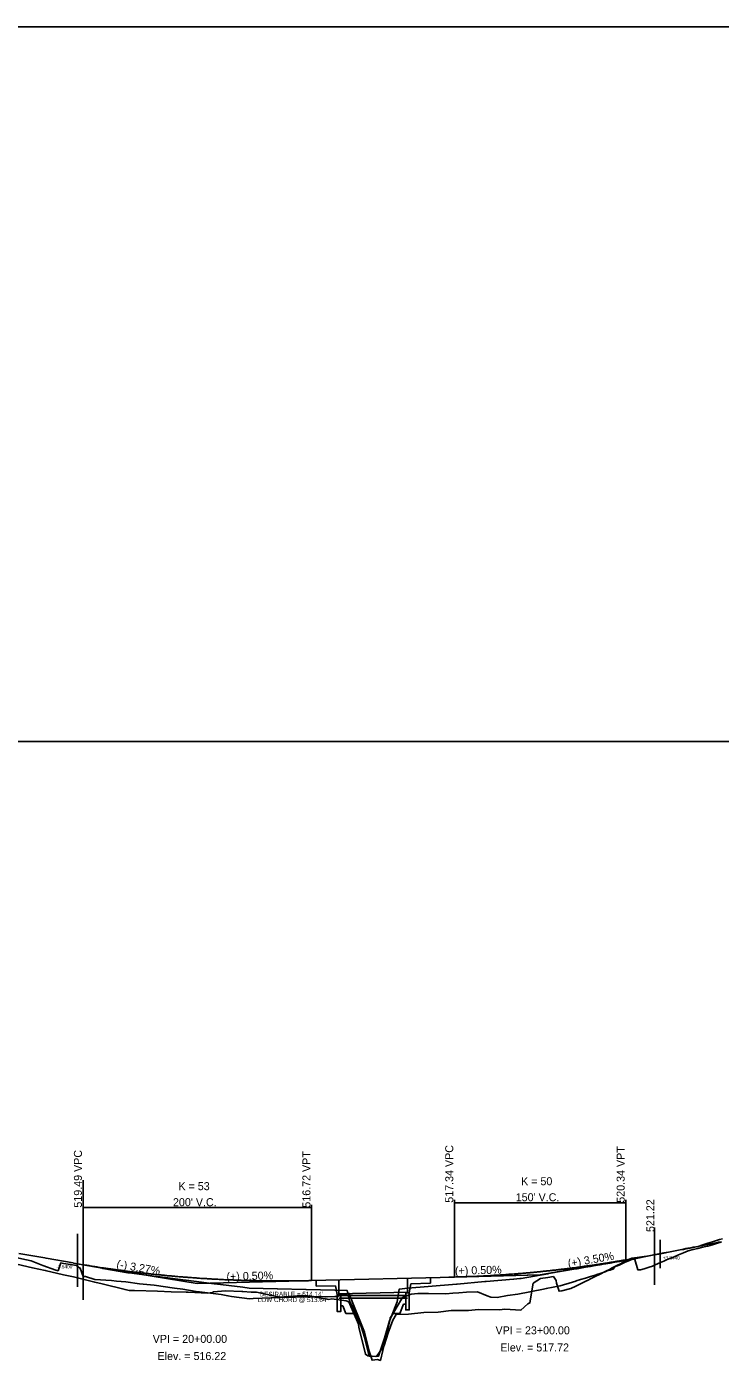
# Model space of a CAD drawing. Extents: x 2167726 to 2171326, y 1079832 to 1082032.
# Drawn here: x 2169001 to 2169608, y 1080863 to 1082032 of the extents above; entities that cross this region are included whole.
import ezdxf

# ---------------------------------------------------------------- set-up
doc = ezdxf.new("R2010")
doc.units = 0
for name, color, linetype in [('BR_CONCRETE', 7, 'Continuous'), ('BR_EXIST_GROUND_LT', 7, 'Continuous'), ('BR_EXIST_GROUND_RT', 7, 'Continuous'), ('BR_USER NOTES', 7, 'Continuous'), ('RD_DDB_GradeTX', 7, 'Continuous'), ('RD_DDB_Profile_EX', 7, 'Continuous'), ('RD_DDB_Profile_Lbl', 7, 'Continuous'), ('RD_DDB_Profile_PR', 7, 'Continuous'), ('RD_DDB_StripGrade', 7, 'Continuous'), ('RD_DDB_VCLbl', 7, 'Continuous'), ('RD_SHT_IplotShp', 7, 'Continuous'), ('RD_SHT_ShtClip', 7, 'Continuous')]:
    doc.layers.add(name, color=color, linetype=linetype)

msp = doc.modelspace()

# ---------------------------------------------------------------- linework, layer by layer
at = {"layer": 'BR_CONCRETE'}
for p, q in [((2169254.2, 1080935.2), (2169254.2, 1080930.2)), ((2169254.2, 1080930.2), (2169271.2, 1080930.6)), ((2169272.7, 1080923), (2169271.2, 1080930.6)), ((2169274.2, 1080923.4), (2169274.2, 1080935.7)), ((2169334.2, 1080924.9), (2169334.2, 1080937.2)), ((2169335.7, 1080924.5), (2169337.2, 1080932.3)), ((2169337.2, 1080932.3), (2169354.2, 1080932.7)), ((2169354.2, 1080932.7), (2169354.2, 1080937.7)), ((2169274.2, 1080923.4), (2169334.2, 1080924.9)), ((2169274.2, 1080923), (2169274.2, 1080923.4)), ((2169334.2, 1080924.5), (2169334.2, 1080924.9)), ((2169275.7, 1080913), (2169277.7, 1080913)), ((2169332.7, 1080914.5), (2169330.7, 1080914.5))]:
    msp.add_line(p, q, dxfattribs=at)
for points in [[(2169272.7, 1080923), (2169275.7, 1080923), (2169275.7, 1080908), (2169272.7, 1080908)], [(2169335.7, 1080924.5), (2169332.7, 1080924.5), (2169332.7, 1080909.5), (2169335.7, 1080909.5)]]:
    msp.add_lwpolyline(points, close=True, dxfattribs=at)
for points in [[(2169277.7, 1080913), (2169280.3, 1080906.4), (2169288.7, 1080906.4)], [(2169330.7, 1080914.5), (2169327.5, 1080906.4), (2169321.2, 1080906.4)]]:
    msp.add_lwpolyline(points, dxfattribs=at)
at = {"layer": 'BR_EXIST_GROUND_LT'}
msp.add_lwpolyline([(2168992.2, 1080949.5), (2169006, 1080946.2), (2169017.1, 1080944), (2169033.1, 1080940.1), (2169041.9, 1080938.3), (2169060.4, 1080933.7), (2169066.8, 1080932.4), (2169087, 1080927.2), (2169090.6, 1080926.5), (2169095.2, 1080926.3), (2169115.5, 1080925.9), (2169127.3, 1080925.3), (2169140.4, 1080925), (2169142.2, 1080925), (2169159.3, 1080924), (2169163.5, 1080924.7), (2169164.3, 1080925.3), (2169175, 1080926.1), (2169189.3, 1080925.6), (2169190.1, 1080925.5), (2169197.3, 1080925.1), (2169201.9, 1080925), (2169222, 1080920.7), (2169241.5, 1080922), (2169242.6, 1080922), (2169246.8, 1080921.9), (2169265.2, 1080918.7), (2169268, 1080919.1), (2169280.4, 1080917.3), (2169282.8, 1080916.5), (2169291.3, 1080896.9), (2169291.7, 1080894.3), (2169297.4, 1080870.7), (2169299.5, 1080869.2), (2169306.9, 1080868.7), (2169313.6, 1080878.3), (2169317.2, 1080889.3), (2169321.4, 1080900.6), (2169324.1, 1080905.4), (2169334.9, 1080905.8), (2169348.4, 1080907.3), (2169361, 1080907.6), (2169372.5, 1080908.9), (2169387.5, 1080908.9), (2169396.3, 1080909.9), (2169414.8, 1080909.5), (2169419.4, 1080910), (2169433.4, 1080909.2), (2169439.6, 1080914.9), (2169441.3, 1080915.5), (2169444.2, 1080932.7), (2169450.5, 1080936.9), (2169457, 1080937.9), (2169461.9, 1080938.6), (2169464.2, 1080935.1), (2169464.7, 1080932.9), (2169466.8, 1080925.8), (2169469.2, 1080926.1), (2169477.1, 1080928.1), (2169481.4, 1080930.2), (2169485.7, 1080932.3), (2169490.1, 1080934.5), (2169492.3, 1080935.5), (2169494.3, 1080936.5), (2169498.5, 1080938.6), (2169502.8, 1080940.8), (2169507.1, 1080943), (2169511.4, 1080945.2), (2169512.7, 1080945.9), (2169515.7, 1080947.3), (2169518.1, 1080948.5), (2169519.9, 1080949.5), (2169524.2, 1080951.7), (2169525.3, 1080952.3), (2169526, 1080952.7), (2169528.5, 1080953.9), (2169530.4, 1080954.8), (2169532.8, 1080955.1), (2169537.1, 1080955.7), (2169541.3, 1080956.3), (2169545.6, 1080956.9), (2169549.4, 1080957.5), (2169549.9, 1080957.6), (2169554.2, 1080958.5), (2169555.3, 1080958.8), (2169558.4, 1080959.3), (2169562.7, 1080960), (2169567, 1080960.8), (2169571.3, 1080961.6), (2169574.6, 1080962.2), (2169575.6, 1080962.5), (2169577.9, 1080963.1), (2169579.8, 1080963.5), (2169582, 1080963.9), (2169584.1, 1080964.3), (2169588.5, 1080965), (2169592.7, 1080966.3), (2169597, 1080967.7), (2169601.2, 1080969), (2169605.5, 1080970.4), (2169607.2, 1080971), (2169609.8, 1080971.5)], dxfattribs=at)
at = {"layer": 'BR_EXIST_GROUND_RT'}
msp.add_lwpolyline([(2168989.8, 1080955.7), (2169004.8, 1080952.3), (2169015.1, 1080948.4), (2169026.3, 1080944.1), (2169028.3, 1080943.7), (2169030.8, 1080950.5), (2169033.1, 1080950), (2169039.3, 1080949.3), (2169044.4, 1080948.2), (2169047.5, 1080946.1), (2169047.8, 1080946), (2169050.4, 1080938.7), (2169052.4, 1080938.8), (2169060.5, 1080936.1), (2169075.2, 1080935.1), (2169079.5, 1080934.7), (2169087.6, 1080934.1), (2169099.6, 1080932.2), (2169112.5, 1080931.2), (2169130.3, 1080928.4), (2169137.5, 1080927.6), (2169149.1, 1080925.7), (2169152, 1080925.4), (2169171, 1080922.8), (2169177, 1080921.8), (2169180.1, 1080921.2), (2169196, 1080919), (2169199.2, 1080919.5), (2169214.8, 1080919.9), (2169221.2, 1080920.2), (2169223.5, 1080920.2), (2169245.8, 1080920.8), (2169253.9, 1080920.8), (2169270.6, 1080921.1), (2169272.3, 1080921.2), (2169282.9, 1080924), (2169296.5, 1080890), (2169300.5, 1080873.3), (2169303.2, 1080865.4), (2169307.9, 1080866), (2169310.4, 1080865.2), (2169318.7, 1080900.3), (2169319, 1080902.5), (2169320.2, 1080904.1), (2169321.9, 1080907), (2169324.2, 1080910.9), (2169329.7, 1080920.2), (2169337.3, 1080923.2), (2169343.3, 1080923.8), (2169352.4, 1080923.7), (2169367.6, 1080923.5), (2169373.9, 1080924.1), (2169379, 1080924.5), (2169385.9, 1080925.1), (2169395.3, 1080925.2), (2169403.9, 1080921.9), (2169407, 1080920.7), (2169412.5, 1080920.2), (2169421.7, 1080922.1), (2169430.8, 1080923.3), (2169453.3, 1080927.7), (2169455.6, 1080928.1), (2169467.8, 1080930.6), (2169478.7, 1080933.7), (2169481.4, 1080934.7), (2169481.9, 1080934.9), (2169485.7, 1080936), (2169490, 1080937.3), (2169494.3, 1080938.6), (2169498.5, 1080939.9), (2169500, 1080940.3), (2169502.8, 1080941.3), (2169507.1, 1080942.9), (2169509, 1080943.6), (2169511.4, 1080944.3), (2169513.5, 1080945), (2169514.2, 1080945.2), (2169515.9, 1080947.3), (2169517.9, 1080948), (2169518.4, 1080948.3), (2169519.3, 1080948.6), (2169519.9, 1080948.9), (2169524.2, 1080950.8), (2169528.5, 1080952.6), (2169531.1, 1080953.7), (2169532.4, 1080953.5), (2169532.8, 1080953.5), (2169533.2, 1080953.5), (2169535.7, 1080944.6), (2169537.1, 1080944.6), (2169538.1, 1080944.6), (2169541.3, 1080945.5), (2169545.6, 1080946.8), (2169548.5, 1080947.6), (2169549.9, 1080948.3), (2169554.2, 1080950.2), (2169558.4, 1080952.2), (2169560.4, 1080953), (2169562.9, 1080954), (2169567, 1080955.7), (2169571.3, 1080957.5), (2169575.6, 1080959.3), (2169579.8, 1080961.1), (2169584.1, 1080962.2), (2169588.4, 1080963.2), (2169592.7, 1080964.2), (2169596.3, 1080965.1), (2169597, 1080965.3), (2169601.2, 1080966.5), (2169604.6, 1080967.5), (2169605.5, 1080967.8), (2169608.9, 1080968.7)], dxfattribs=at)
at = {"layer": 'BR_USER NOTES'}
for p, q in [((2169050.2, 1081022.9), (2169050.2, 1080918.4)), ((2169550.2, 1080981.5), (2169550.2, 1080931.5)), ((2169045.2, 1080976), (2169045.2, 1080929.7)), ((2169555.2, 1080970.8), (2169555.2, 1080945.9)), ((2169550.2, 1080957.6), (2169555.2, 1080958.5)), ((2169050.2, 1080948.9), (2169045.2, 1080949.8)), ((2169274.2, 1080922.2), (2169334.2, 1080922.2)), ((2169274.2, 1080919.7), (2169334.2, 1080919.7))]:
    msp.add_line(p, q, dxfattribs=at)
at = {"layer": 'RD_DDB_GradeTX'}
for p, q in [((2169529, 1080953.9), (2169450.2, 1080940.1)), ((2169525.2, 1080953.2), (2169450.2, 1080940.1)), ((2169071.2, 1080945.5), (2169150.2, 1080932.6)), ((2169230.2, 1080934.6), (2169150.2, 1080932.6)), ((2169370.2, 1080938.1), (2169450.2, 1080940.1)), ((2169375.2, 1080938.2), (2169450.2, 1080940.1))]:
    msp.add_line(p, q, dxfattribs=at)
at = {"layer": 'RD_DDB_Profile_EX'}
msp.add_lwpolyline([(2168993.9, 1080958.9), (2169016.8, 1080954.9), (2169017.8, 1080954.7), (2169041.6, 1080950.5), (2169041.9, 1080950.4), (2169066.8, 1080946), (2169067.6, 1080945.8), (2169089.4, 1080941.9), (2169089.9, 1080941.8), (2169090.5, 1080941.8), (2169114.9, 1080938.7), (2169115.5, 1080938.6), (2169139.9, 1080935.6), (2169140.5, 1080935.5), (2169164.9, 1080932.4), (2169165.5, 1080932.4), (2169189.9, 1080929.3), (2169195.5, 1080928.6), (2169220.1, 1080928), (2169220.5, 1080928), (2169245.2, 1080927.3), (2169245.5, 1080927.3), (2169270.5, 1080926.7), (2169281.4, 1080926.4), (2169283.4, 1080917.5), (2169290.4, 1080902.9), (2169293.7, 1080895), (2169296.4, 1080885.6), (2169300.7, 1080869.1), (2169306.1, 1080868.8), (2169308.8, 1080869.1), (2169313.9, 1080884.7), (2169318.3, 1080899.8), (2169320.3, 1080904), (2169325, 1080916.4), (2169327, 1080927.7), (2169334.4, 1080928.4), (2169352.2, 1080929.9), (2169377, 1080932), (2169377.6, 1080932.1), (2169401.9, 1080934.2), (2169403.1, 1080934.3), (2169426.9, 1080936.3), (2169427.3, 1080936.3), (2169432.5, 1080936.8), (2169433.7, 1080937), (2169457.1, 1080941.1), (2169457.7, 1080941.2), (2169481.4, 1080945.3), (2169481.7, 1080945.3), (2169482.6, 1080945.5), (2169485.7, 1080946), (2169490, 1080946.8), (2169494.3, 1080947.5), (2169498.5, 1080948.2), (2169502.8, 1080949), (2169506.8, 1080949.7), (2169507.1, 1080949.7), (2169507.6, 1080949.8), (2169511.4, 1080950.4), (2169515.7, 1080951.2), (2169519.9, 1080951.9), (2169524.2, 1080952.6), (2169525.9, 1080952.9), (2169526.7, 1080953), (2169528.5, 1080953.4), (2169532.8, 1080954.2), (2169537.1, 1080955), (2169541.3, 1080955.9), (2169545.6, 1080956.7), (2169550.1, 1080957.6), (2169551.6, 1080957.9), (2169554.2, 1080958.3), (2169558.4, 1080959.2), (2169562.7, 1080960), (2169567, 1080960.8), (2169571.3, 1080961.6), (2169574.3, 1080962.2), (2169575.6, 1080962.4), (2169576.7, 1080962.6), (2169579.8, 1080963.2), (2169581, 1080963.4), (2169581.5, 1080963.5), (2169584.1, 1080964.1), (2169588.4, 1080964.9), (2169592.7, 1080965.8), (2169597, 1080966.6), (2169601.2, 1080967.5), (2169604, 1080968), (2169605.5, 1080968.4), (2169606.4, 1080968.6), (2169608.8, 1080969)], dxfattribs=at)
at = {"layer": 'RD_DDB_Profile_PR'}
for p, q in [((2169525.2, 1080953.2), (2169550.2, 1080957.6)), ((2169250.2, 1080935.1), (2169375.2, 1080938.2))]:
    msp.add_line(p, q, dxfattribs=at)
for points in [[(2169375.2, 1080938.2), (2169378.2, 1080938.3), (2169381.2, 1080938.4), (2169384.2, 1080938.5), (2169387.2, 1080938.6), (2169390.2, 1080938.7), (2169393.2, 1080938.8), (2169396.2, 1080939), (2169399.2, 1080939.1), (2169402.2, 1080939.2), (2169405.2, 1080939.4), (2169408.2, 1080939.6), (2169411.2, 1080939.8), (2169414.2, 1080939.9), (2169417.2, 1080940.1), (2169420.2, 1080940.3), (2169423.2, 1080940.6), (2169426.2, 1080940.8), (2169429.2, 1080941), (2169432.2, 1080941.3), (2169435.2, 1080941.5), (2169438.2, 1080941.8), (2169441.2, 1080942), (2169444.2, 1080942.3), (2169447.2, 1080942.6), (2169450.2, 1080942.9), (2169453.2, 1080943.2), (2169456.2, 1080943.5), (2169459.2, 1080943.8), (2169462.2, 1080944.2), (2169465.2, 1080944.5), (2169468.2, 1080944.9), (2169471.2, 1080945.2), (2169474.2, 1080945.6), (2169477.2, 1080946), (2169480.2, 1080946.3), (2169483.2, 1080946.7), (2169486.2, 1080947.1), (2169489.2, 1080947.6), (2169492.2, 1080948), (2169495.2, 1080948.4), (2169498.2, 1080948.8), (2169501.2, 1080949.3), (2169504.2, 1080949.8), (2169507.2, 1080950.2), (2169510.2, 1080950.7), (2169513.2, 1080951.2), (2169516.2, 1080951.7), (2169519.2, 1080952.2), (2169522.2, 1080952.7), (2169525.2, 1080953.2)], [(2169050.2, 1080948.9), (2169054.2, 1080948.3), (2169058.2, 1080947.7), (2169062.2, 1080947), (2169066.2, 1080946.4), (2169070.2, 1080945.9), (2169074.2, 1080945.3), (2169078.2, 1080944.7), (2169082.2, 1080944.2), (2169086.2, 1080943.7), (2169090.2, 1080943.1), (2169094.2, 1080942.7), (2169098.2, 1080942.2), (2169102.2, 1080941.7), (2169106.2, 1080941.3), (2169110.2, 1080940.8), (2169114.2, 1080940.4), (2169118.2, 1080940), (2169122.2, 1080939.6), (2169126.2, 1080939.2), (2169130.2, 1080938.9), (2169134.2, 1080938.5), (2169138.2, 1080938.2), (2169142.2, 1080937.9), (2169146.2, 1080937.6), (2169150.2, 1080937.3), (2169154.2, 1080937), (2169158.2, 1080936.8), (2169162.2, 1080936.5), (2169166.2, 1080936.3), (2169170.2, 1080936.1), (2169174.2, 1080935.9), (2169178.2, 1080935.7), (2169182.2, 1080935.6), (2169186.2, 1080935.4), (2169190.2, 1080935.3), (2169194.2, 1080935.2), (2169198.2, 1080935.1), (2169202.2, 1080935), (2169206.2, 1080934.9), (2169210.2, 1080934.8), (2169214.2, 1080934.8), (2169218.2, 1080934.8), (2169222.2, 1080934.8), (2169226.2, 1080934.8), (2169230.2, 1080934.8), (2169234.2, 1080934.8), (2169238.2, 1080934.9), (2169242.2, 1080934.9), (2169246.2, 1080935), (2169250.2, 1080935.1)]]:
    msp.add_spline(points, degree=3, dxfattribs=at)
at = {"layer": 'RD_DDB_VCLbl'}
for p, q in [((2169050.2, 1081001.4), (2169050.2, 1080948.9)), ((2169250.2, 1081001.4), (2169250.2, 1080935.1)), ((2169375.2, 1081005.7), (2169375.2, 1080938.2)), ((2169375.2, 1081003.2), (2169525.2, 1081003.2)), ((2169525.2, 1081005.7), (2169525.2, 1080953.2)), ((2169050.2, 1080998.9), (2169250.2, 1080998.9))]:
    msp.add_line(p, q, dxfattribs=at)
at = {"layer": 'RD_SHT_IplotShp'}
msp.add_lwpolyline([(2167726.1, 1079832), (2171326.1, 1079832), (2171326.1, 1082032), (2167726.1, 1082032)], close=True, dxfattribs=at)
at = {"layer": 'RD_SHT_ShtClip'}
msp.add_lwpolyline([(2168412.7, 1081406.6), (2170212.7, 1081406.6), (2170212.7, 1080306.6), (2168412.7, 1080306.6)], close=True, dxfattribs=at)

# ---------------------------------------------------------------- texts
at = {"layer": 'BR_USER NOTES'}
for s, height, p in [('+3.8440', 3, (2169557.5, 1080953.5)), ('-3.5400', 3, (2169026.8, 1080945.8)), ("LOW CHORD @ 513.64'", 4, (2169203.2, 1080916.3)), ("DESIRABLE = 514.14'", 4, (2169204.8, 1080921.3))]:
    msp.add_text(s, height=height, dxfattribs=at).set_placement(p)
at = {"layer": 'RD_DDB_GradeTX'}
for s, rotation, p in [('(-) 3.27%', 350.7143, (2169079.1, 1080946.2)), ('(+) 3.50%', 9.9229, (2169475.1, 1080946.5)), ('(+) 0.50%', 1.4321, (2169175.8, 1080935.2)), ('(+) 0.50%', 1.4321, (2169375.8, 1080940.2))]:
    msp.add_text(s, height=7, rotation=rotation, dxfattribs=at).set_placement(p)
at = {"layer": 'RD_DDB_Profile_Lbl'}
msp.add_text('521.22', height=7, rotation=90, dxfattribs=at).set_placement((2169550.2, 1080977.6))
for s, p in [('VPI = 23+00.00', (2169411.2, 1080888.1)), ('VPI = 20+00.00', (2169111.2, 1080880.6)), ('Elev. = 516.22', (2169115.4, 1080865.6)), ('Elev. = 517.72', (2169415.4, 1080873.1))]:
    msp.add_text(s, height=7, dxfattribs=at).set_placement(p)
at = {"layer": 'RD_DDB_StripGrade'}
for s, p in [('519.49 VPC', (2169049.2, 1080998.9)), ('516.72 VPT', (2169249.2, 1080998.9)), ('517.34 VPC', (2169374.2, 1081003.2)), ('520.34 VPT', (2169524.2, 1081003.2))]:
    msp.add_text(s, height=7, rotation=90, dxfattribs=at).set_placement(p)
at = {"layer": 'RD_DDB_VCLbl'}
for s, p in [('K = 50', (2169433.6, 1081018.5)), ('K = 53', (2169133.7, 1081014.2)), ("150' V.C.", (2169428.9, 1081004.5)), ("200' V.C.", (2169128.9, 1081000.2))]:
    msp.add_text(s, height=7, dxfattribs=at).set_placement(p)

doc.saveas('drawing.dxf')
